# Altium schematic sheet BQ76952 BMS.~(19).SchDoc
size A3; SheetNumber: 9; SheetTotal: 9
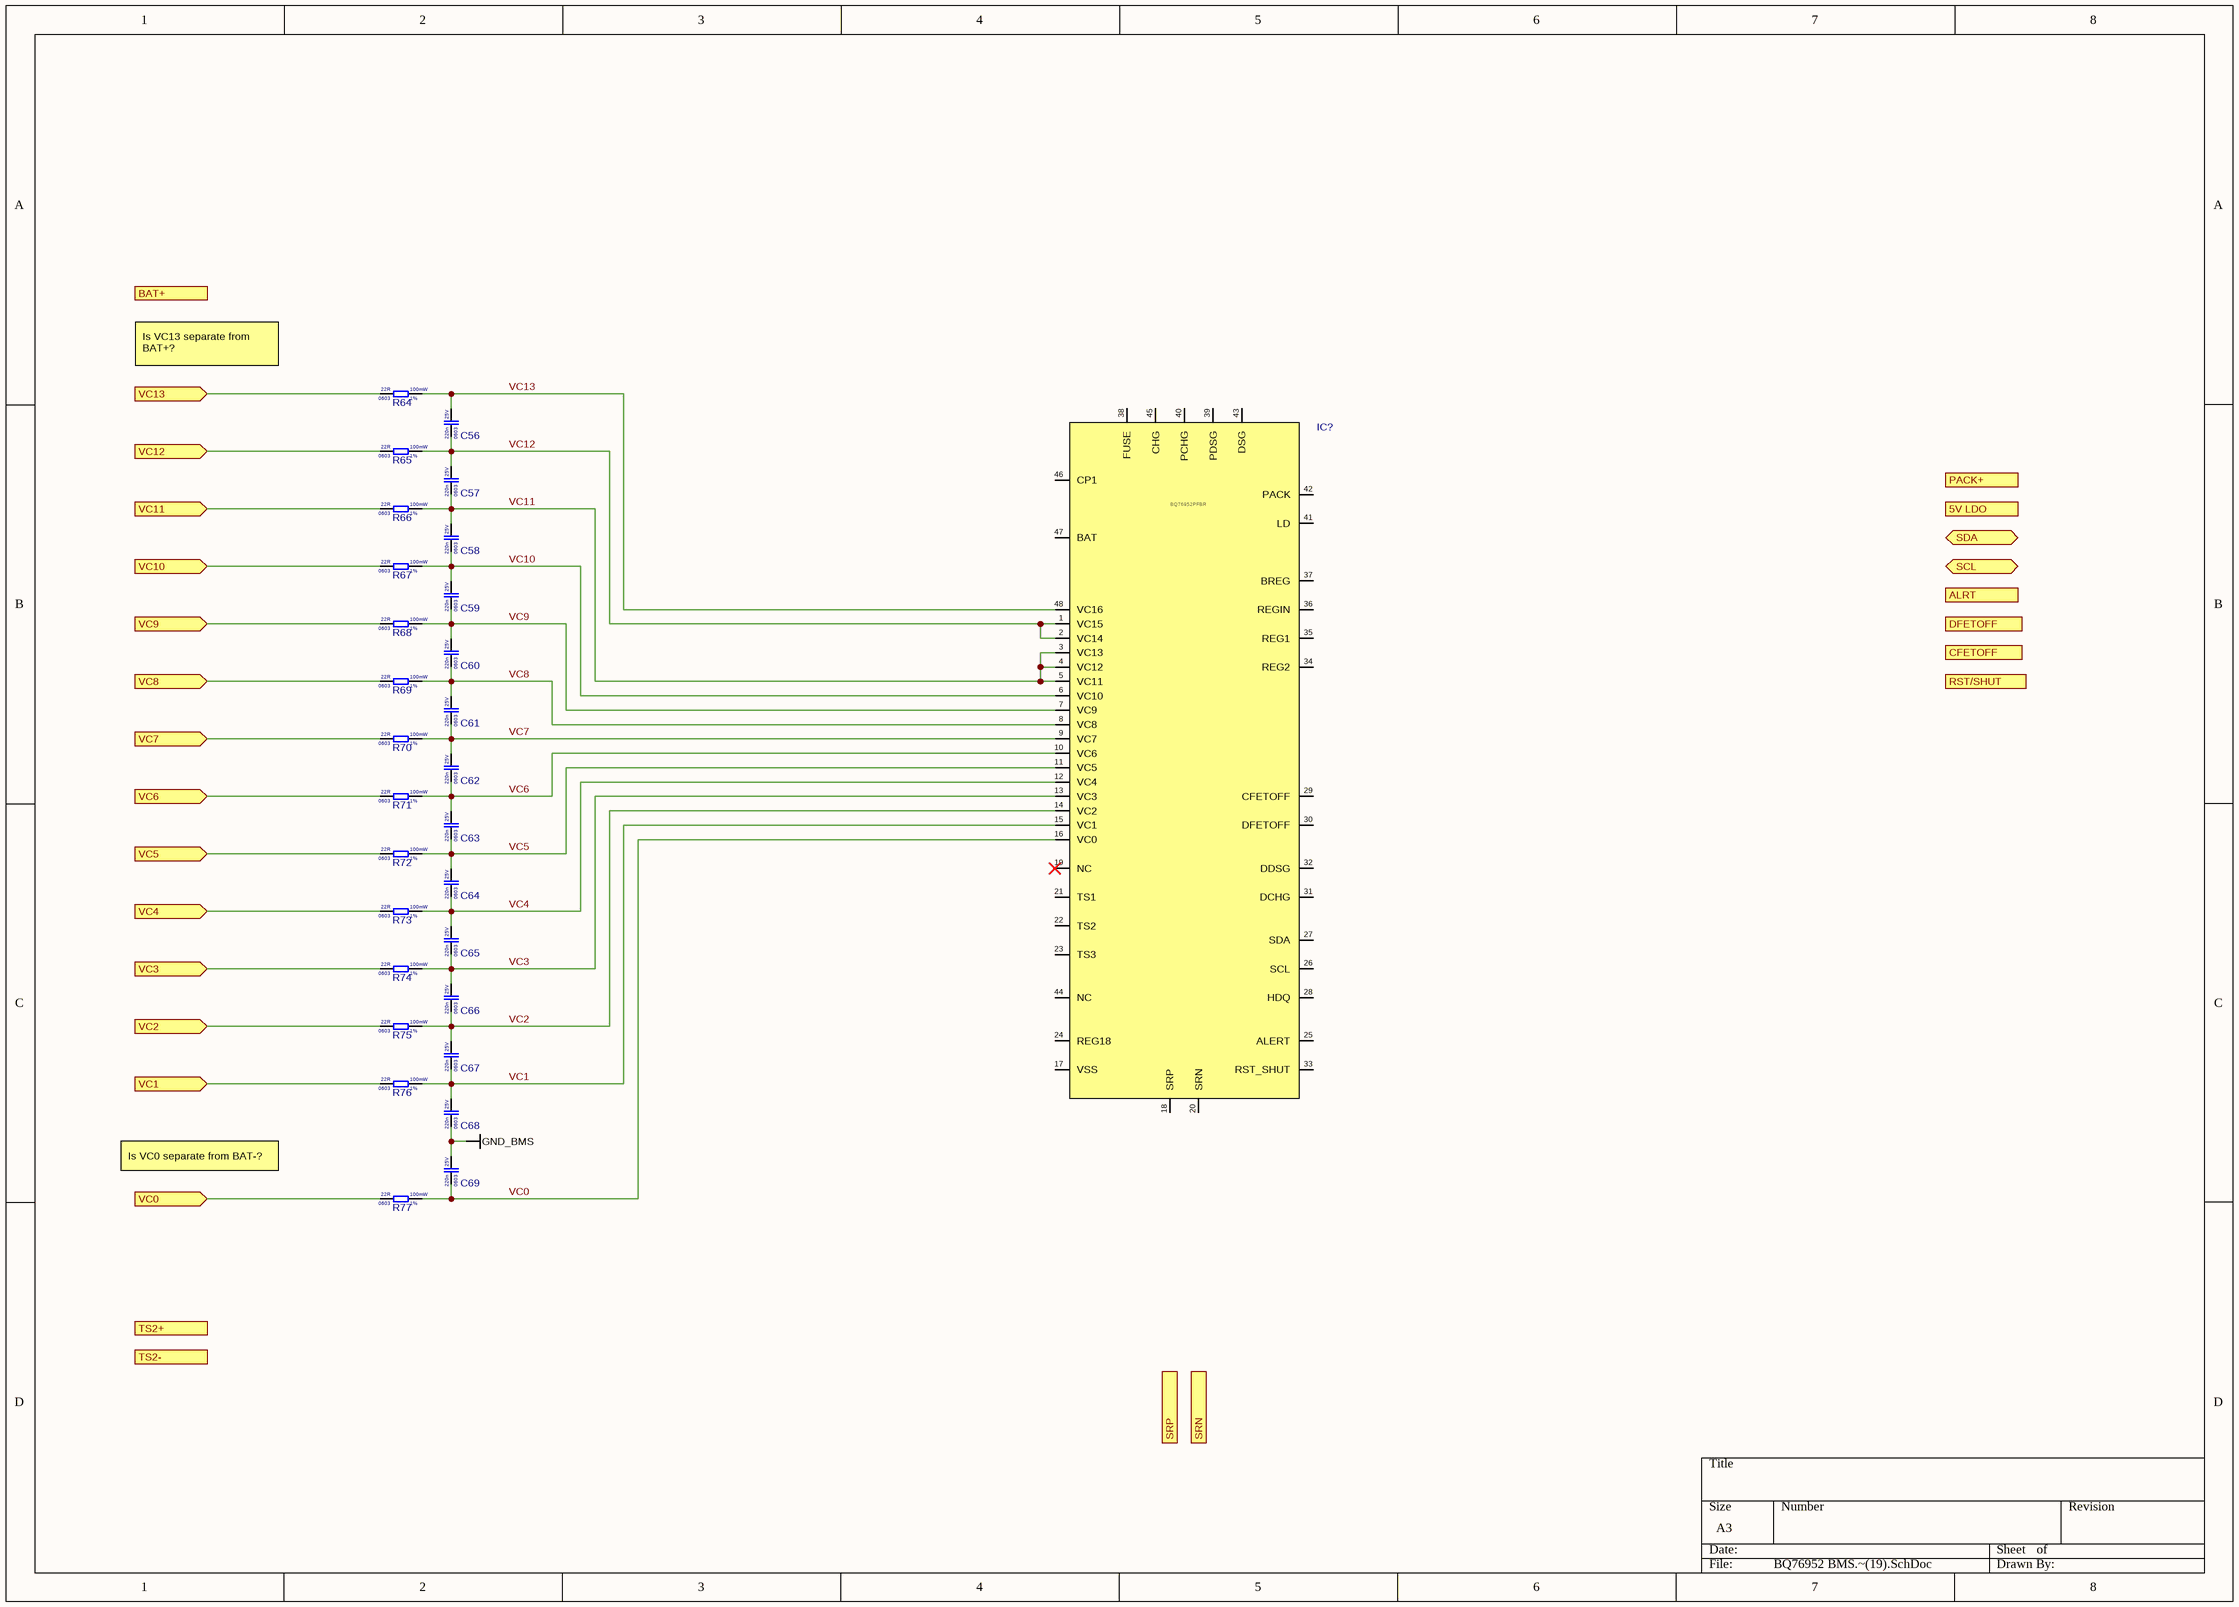
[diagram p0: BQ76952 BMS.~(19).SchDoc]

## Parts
C56  Voltage Rating: 25V  Case Code (Imperial): 0603  Capacitance: 220n  [CAP 0603]  (hidden comment: CL10B224KA8NNNC)
C57  Voltage Rating: 25V  Case Code (Imperial): 0603  Capacitance: 220n  [CAP 0603]  (hidden comment: CL10B224KA8NNNC)
C58  Voltage Rating: 25V  Case Code (Imperial): 0603  Capacitance: 220n  [CAP 0603]  (hidden comment: CL10B224KA8NNNC)
C59  Voltage Rating: 25V  Case Code (Imperial): 0603  Capacitance: 220n  [CAP 0603]  (hidden comment: CL10B224KA8NNNC)
C60  Voltage Rating: 25V  Case Code (Imperial): 0603  Capacitance: 220n  [CAP 0603]  (hidden comment: CL10B224KA8NNNC)
C61  Voltage Rating: 25V  Case Code (Imperial): 0603  Capacitance: 220n  [CAP 0603]  (hidden comment: CL10B224KA8NNNC)
C62  Voltage Rating: 25V  Case Code (Imperial): 0603  Capacitance: 220n  [CAP 0603]  (hidden comment: CL10B224KA8NNNC)
C63  Voltage Rating: 25V  Case Code (Imperial): 0603  Capacitance: 220n  [CAP 0603]  (hidden comment: CL10B224KA8NNNC)
C64  Voltage Rating: 25V  Case Code (Imperial): 0603  Capacitance: 220n  [CAP 0603]  (hidden comment: CL10B224KA8NNNC)
C65  Voltage Rating: 25V  Case Code (Imperial): 0603  Capacitance: 220n  [CAP 0603]  (hidden comment: CL10B224KA8NNNC)
C66  Voltage Rating: 25V  Case Code (Imperial): 0603  Capacitance: 220n  [CAP 0603]  (hidden comment: CL10B224KA8NNNC)
C67  Voltage Rating: 25V  Case Code (Imperial): 0603  Capacitance: 220n  [CAP 0603]  (hidden comment: CL10B224KA8NNNC)
C68  Voltage Rating: 25V  Case Code (Imperial): 0603  Capacitance: 220n  [CAP 0603]  (hidden comment: CL10B224KA8NNNC)
C69  Voltage Rating: 25V  Case Code (Imperial): 0603  Capacitance: 220n  [CAP 0603]  (hidden comment: CL10B224KA8NNNC)
IC?  BQ76952PFBR  [TQFP-48 PFB]
R64  Resistance Tolerance: 1%  Resistance: 22R  Power Rating: 100mW  Case Code (Imperial): 0603  [RES_0603]  (hidden comment: 0603WAF220JT5E)
R65  Resistance Tolerance: 1%  Resistance: 22R  Power Rating: 100mW  Case Code (Imperial): 0603  [RES_0603]  (hidden comment: 0603WAF220JT5E)
R66  Resistance Tolerance: 1%  Resistance: 22R  Power Rating: 100mW  Case Code (Imperial): 0603  [RES_0603]  (hidden comment: 0603WAF220JT5E)
R67  Resistance Tolerance: 1%  Resistance: 22R  Power Rating: 100mW  Case Code (Imperial): 0603  [RES_0603]  (hidden comment: 0603WAF220JT5E)
R68  Resistance Tolerance: 1%  Resistance: 22R  Power Rating: 100mW  Case Code (Imperial): 0603  [RES_0603]  (hidden comment: 0603WAF220JT5E)
R69  Resistance Tolerance: 1%  Resistance: 22R  Power Rating: 100mW  Case Code (Imperial): 0603  [RES_0603]  (hidden comment: 0603WAF220JT5E)
R70  Resistance Tolerance: 1%  Resistance: 22R  Power Rating: 100mW  Case Code (Imperial): 0603  [RES_0603]  (hidden comment: 0603WAF220JT5E)
R71  Resistance Tolerance: 1%  Resistance: 22R  Power Rating: 100mW  Case Code (Imperial): 0603  [RES_0603]  (hidden comment: 0603WAF220JT5E)
R72  Resistance Tolerance: 1%  Resistance: 22R  Power Rating: 100mW  Case Code (Imperial): 0603  [RES_0603]  (hidden comment: 0603WAF220JT5E)
R73  Resistance Tolerance: 1%  Resistance: 22R  Power Rating: 100mW  Case Code (Imperial): 0603  [RES_0603]  (hidden comment: 0603WAF220JT5E)
R74  Resistance Tolerance: 1%  Resistance: 22R  Power Rating: 100mW  Case Code (Imperial): 0603  [RES_0603]  (hidden comment: 0603WAF220JT5E)
R75  Resistance Tolerance: 1%  Resistance: 22R  Power Rating: 100mW  Case Code (Imperial): 0603  [RES_0603]  (hidden comment: 0603WAF220JT5E)
R76  Resistance Tolerance: 1%  Resistance: 22R  Power Rating: 100mW  Case Code (Imperial): 0603  [RES_0603]  (hidden comment: 0603WAF220JT5E)
R77  Resistance Tolerance: 1%  Resistance: 22R  Power Rating: 100mW  Case Code (Imperial): 0603  [RES_0603]  (hidden comment: 0603WAF220JT5E)

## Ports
5V LDO (out, see BMS[3A]), ALRT (out, see BMS[3B]), BAT+ (in, see BMS[2A], BMS[1A]), CFETOFF (in, see BMS[3C]), DFETOFF (in, see BMS[3B]), PACK+ (out, see BMS[3A], BMS[8A], Charger BQ25756[1A], CHARGER[1B], Power distribution[3A]), RST/SHUT (in, see BMS[3B]), SCL (bidir, see BMS[3C], BMS[8C]), SDA (bidir, see BMS[3C], BMS[8C]), SRN (in, see BMS[3C]), SRP (in, see BMS[2C]), TS2+ (in, see BMS[2C], BMS[1C]), TS2- (in, see BMS[2C], BMS[1C]), VC0 (in, see BMS[2C], BMS[1C]), VC1 (in, see BMS[2B], BMS[1B]), VC2 (in, see BMS[2B], BMS[1B]), VC3 (in, see BMS[2B], BMS[1B]), VC4 (in, see BMS[2B], BMS[1B]), VC5 (in, see BMS[2B], BMS[1B]), VC6 (in, see BMS[2B], BMS[1B]), VC7 (in, see BMS[2B], BMS[1B]), VC8 (in, see BMS[2B], BMS[1B]), VC9 (in, see BMS[2B], BMS[1B]), VC10 (in, see BMS[2B], BMS[1B]), VC11 (in, see BMS[2B], BMS[1B]), VC12 (in, see BMS[2B], BMS[1B]), VC13 (in, see BMS[2B], BMS[1B])

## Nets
GND_BMS: C68.1 C69.2
VC0: R77.1 ; port VC0
VC0: C69.1 IC?.16(VC0) R77.2  [a separate net that carries the same name]
VC1: R76.1 ; port VC1
VC1: C67.1 C68.2 IC?.15(VC1) R76.2  [a separate net that carries the same name]
VC2: R75.1 ; port VC2
VC2: C66.1 C67.2 IC?.14(VC2) R75.2  [a separate net that carries the same name]
VC3: R74.1 ; port VC3
VC3: C65.1 C66.2 IC?.13(VC3) R74.2  [a separate net that carries the same name]
VC4: R73.1 ; port VC4
VC4: C64.1 C65.2 IC?.12(VC4) R73.2  [a separate net that carries the same name]
VC5: R72.1 ; port VC5
VC5: C63.1 C64.2 IC?.11(VC5) R72.2  [a separate net that carries the same name]
VC6: R71.1 ; port VC6
VC6: C62.1 C63.2 IC?.10(VC6) R71.2  [a separate net that carries the same name]
VC7: R70.1 ; port VC7
VC7: C61.1 C62.2 IC?.9(VC7) R70.2  [a separate net that carries the same name]
VC8: R69.1 ; port VC8
VC8: C60.1 C61.2 IC?.8(VC8) R69.2  [a separate net that carries the same name]
VC9: R68.1 ; port VC9
VC9: C59.1 C60.2 IC?.7(VC9) R68.2  [a separate net that carries the same name]
VC10: R67.1 ; port VC10
VC10: C58.1 C59.2 IC?.6(VC10) R67.2  [a separate net that carries the same name]
VC11: R66.1 ; port VC11
VC11: C57.1 C58.2 IC?.3(VC13) IC?.4(VC12) IC?.5(VC11) R66.2  [a separate net that carries the same name]
VC12: R65.1 ; port VC12
VC12: C56.1 C57.2 IC?.1(VC15) IC?.2(VC14) R65.2  [a separate net that carries the same name]
VC13: R64.1 ; port VC13
VC13: C56.2 IC?.48(VC16) R64.2  [a separate net that carries the same name]

Not connected (* = marked no-connect by the designer): IC? 17(VSS) 18(SRP) 19(NC)* 20(SRN) 21(TS1) 22(TS2) 23(TS3) 24(REG18) 25(ALERT) 26(SCL) 27(SDA) 28(HDQ) 29(CFETOFF) 30(DFETOFF) 31(DCHG) 32(DDSG) 33(RST_SHUT) 34(REG2) 35(REG1) 36(REGIN) 37(BREG) 38(FUSE) 39(PDSG) 40(PCHG) 41(LD) 42(PACK) 43(DSG) 44(NC) 45(CHG) 46(CP1) 47(BAT)

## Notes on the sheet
- Is VC13 separate from BAT+?
- Is VC0 separate from BAT-?

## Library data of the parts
C56-C69 = CL10B224KA8NNNC: Cap 220nF 25V 0603 X7R; Manufacturer: Samsung
IC? = BQ76952PFBR: BMS IC 3~16s; Manufacturer: Texas Instruments
R64-R77 = 0603WAF220JT5E: Res 22R 0603 1% 100mW 75V; Manufacturer: Uni-Royal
